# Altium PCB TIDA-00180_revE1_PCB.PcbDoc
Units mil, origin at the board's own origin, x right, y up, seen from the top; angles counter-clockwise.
Board outline 3535 x 2012 mil, 4 copper layers (Top Layer, mid layer 1-GND, mid layer 2-VCC, Bottom Layer), stack 90 mil thick; 92 components, 45 nets, 244 pads, 119 vias.
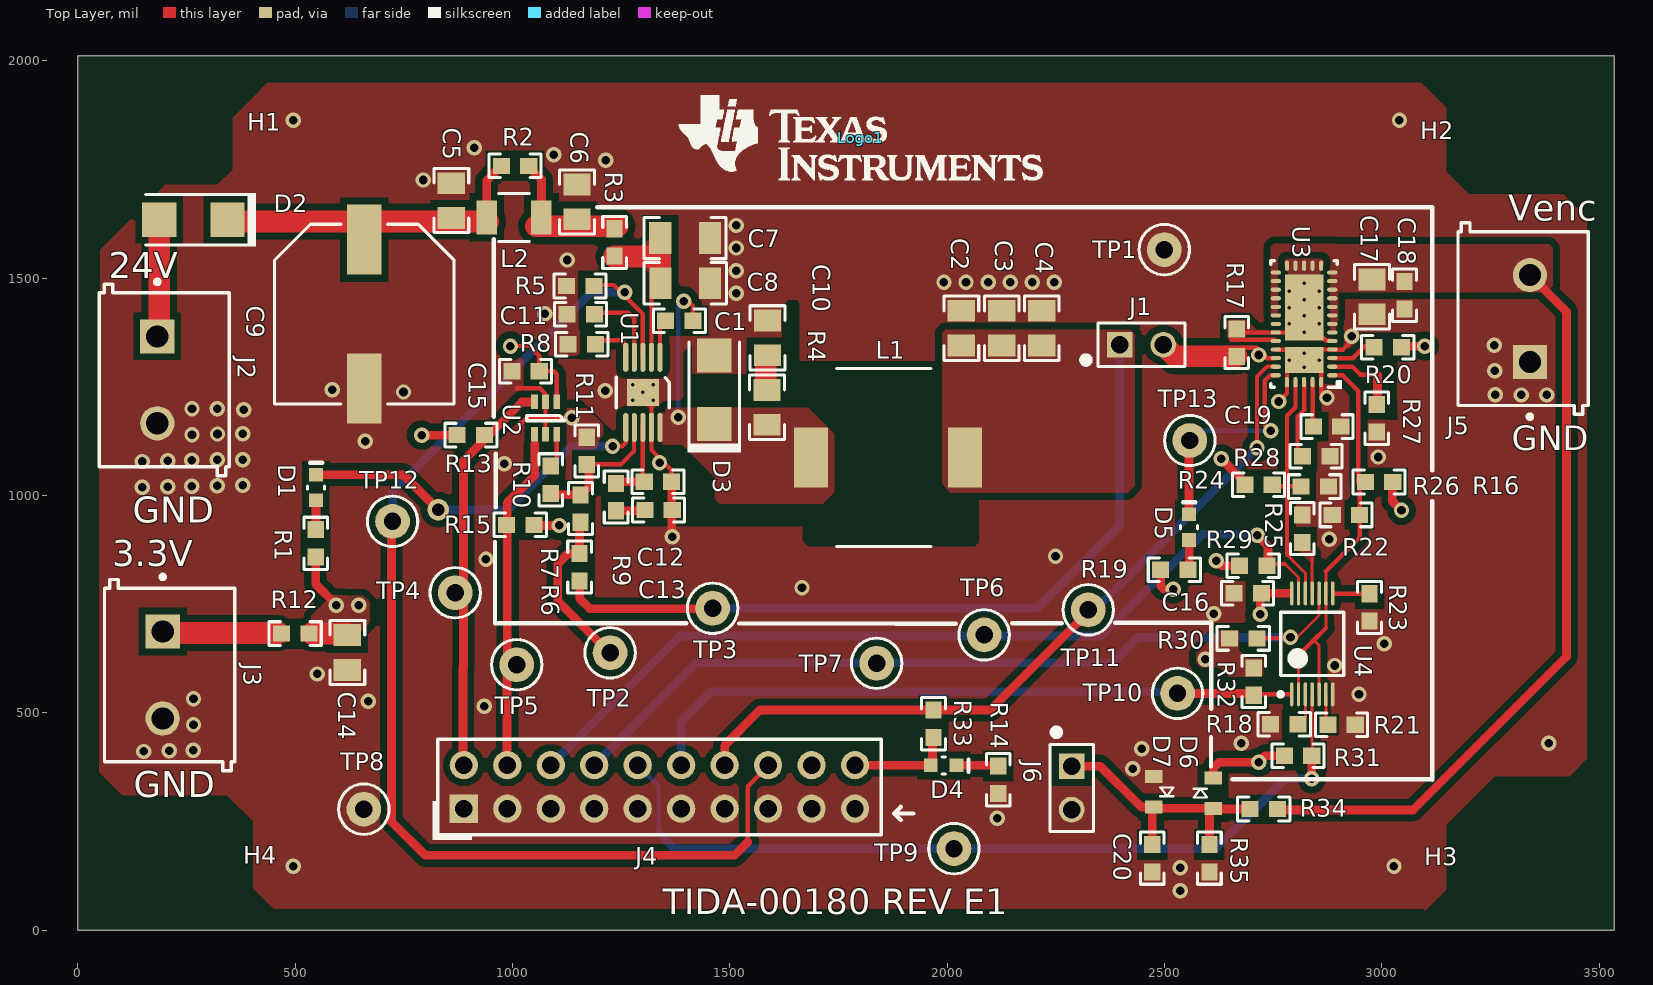
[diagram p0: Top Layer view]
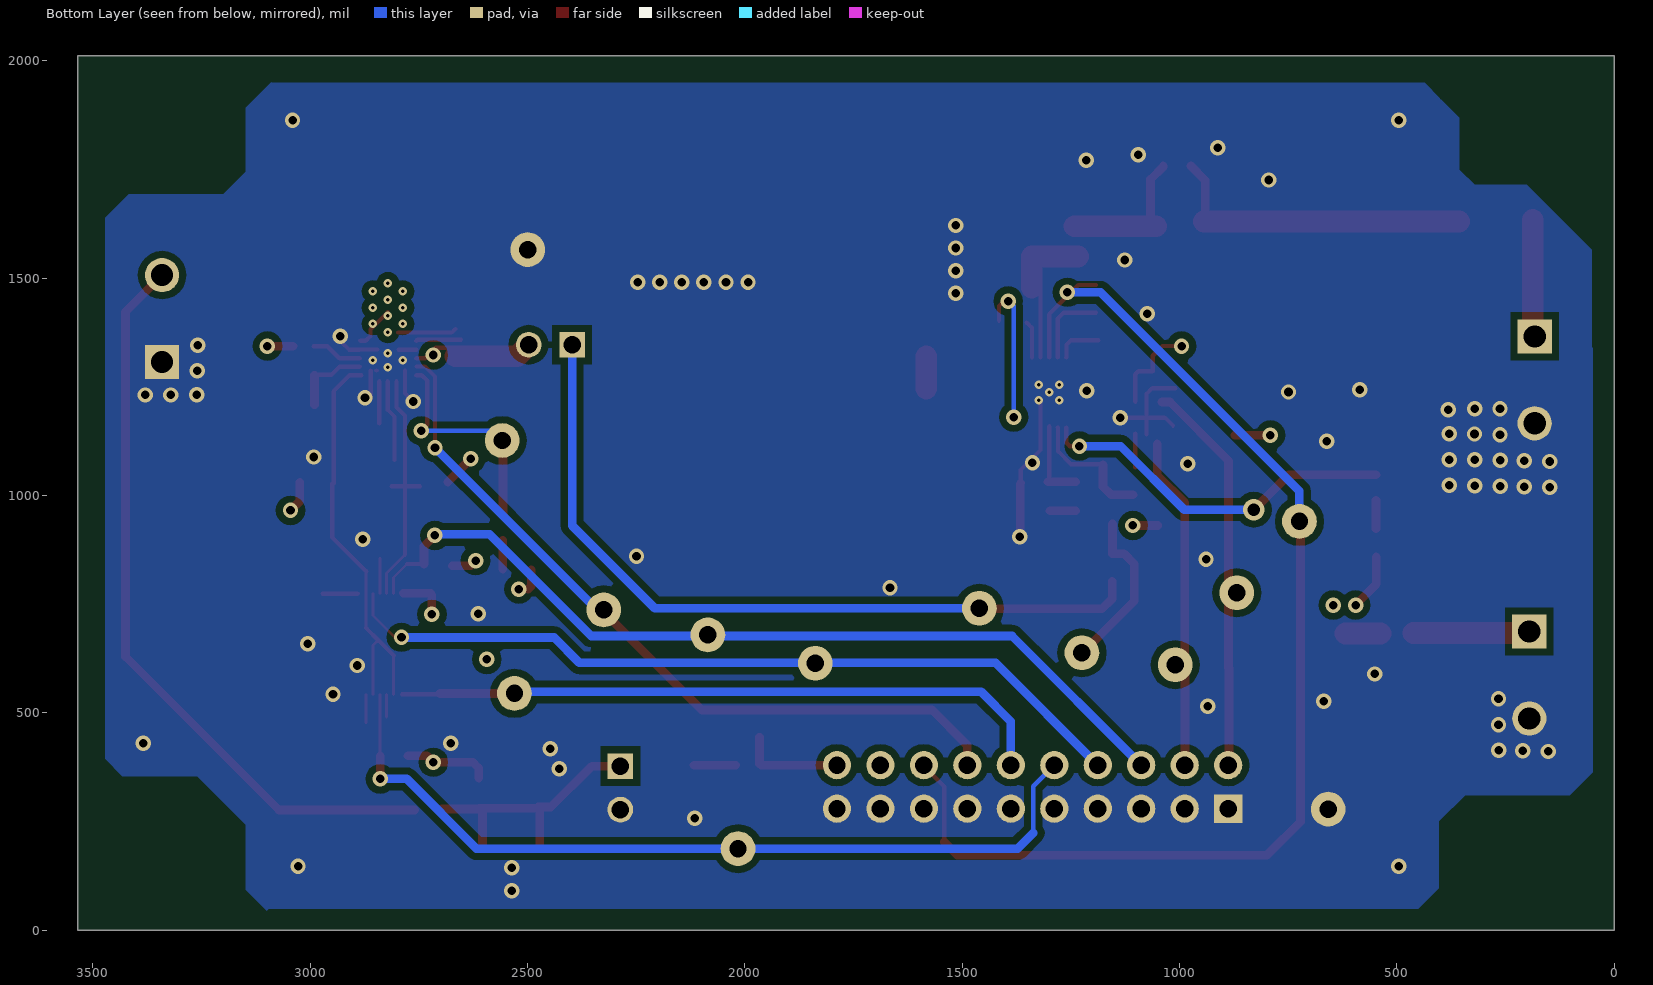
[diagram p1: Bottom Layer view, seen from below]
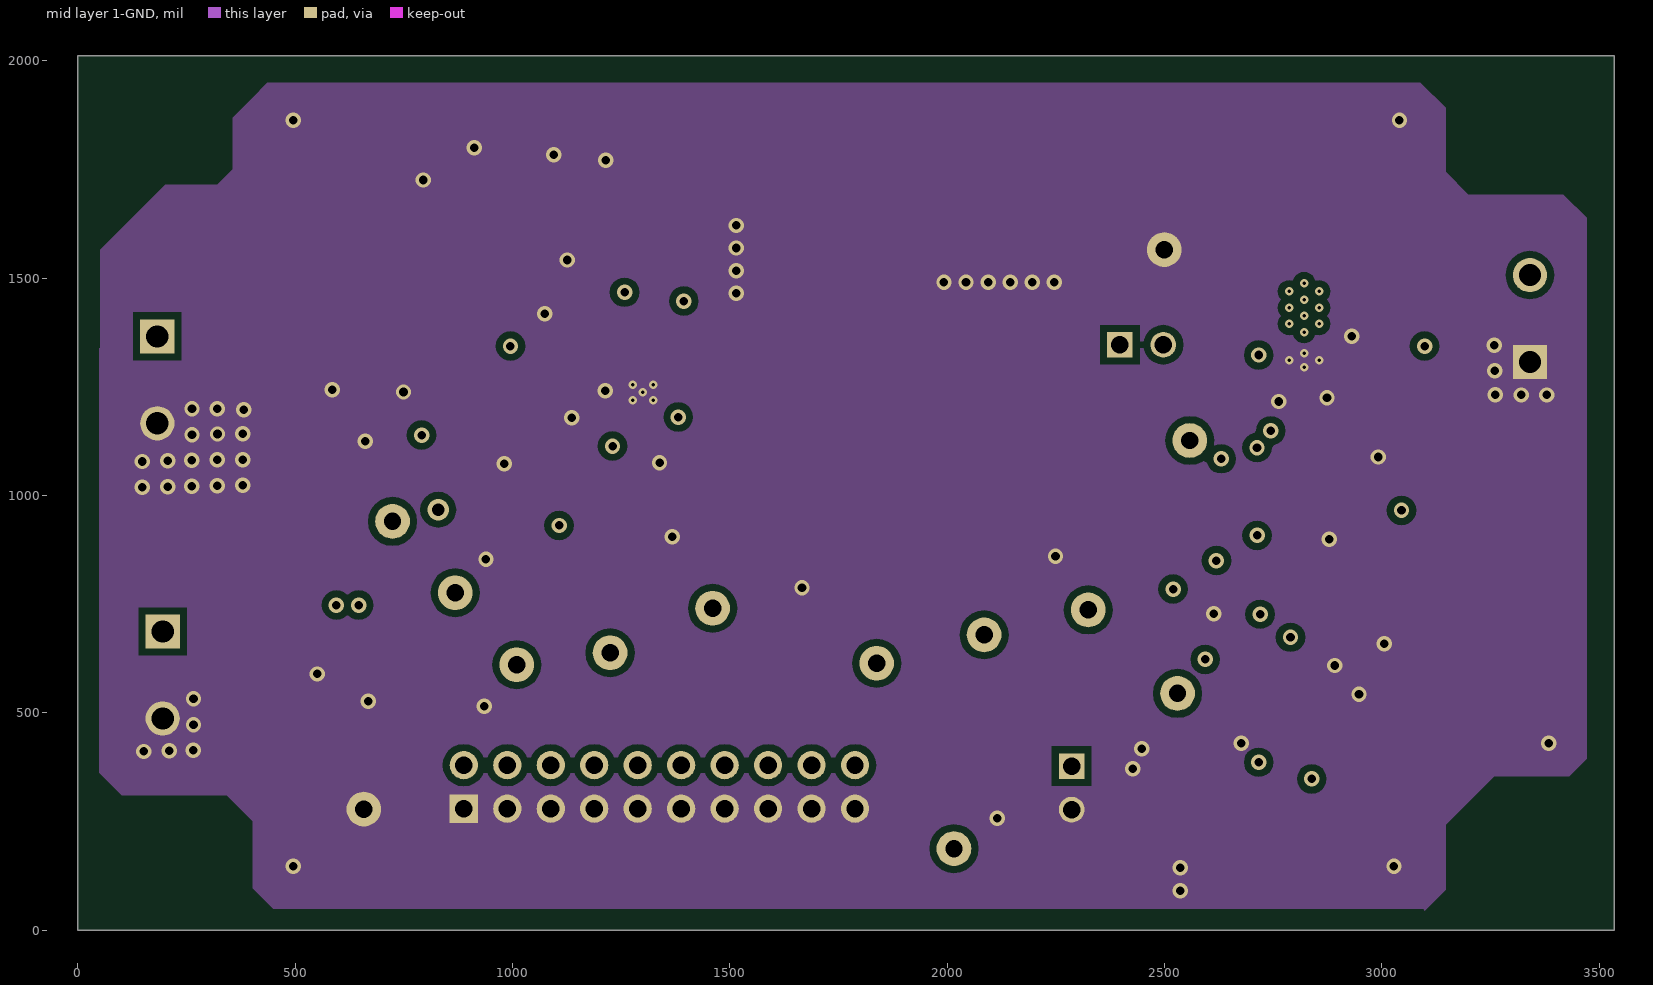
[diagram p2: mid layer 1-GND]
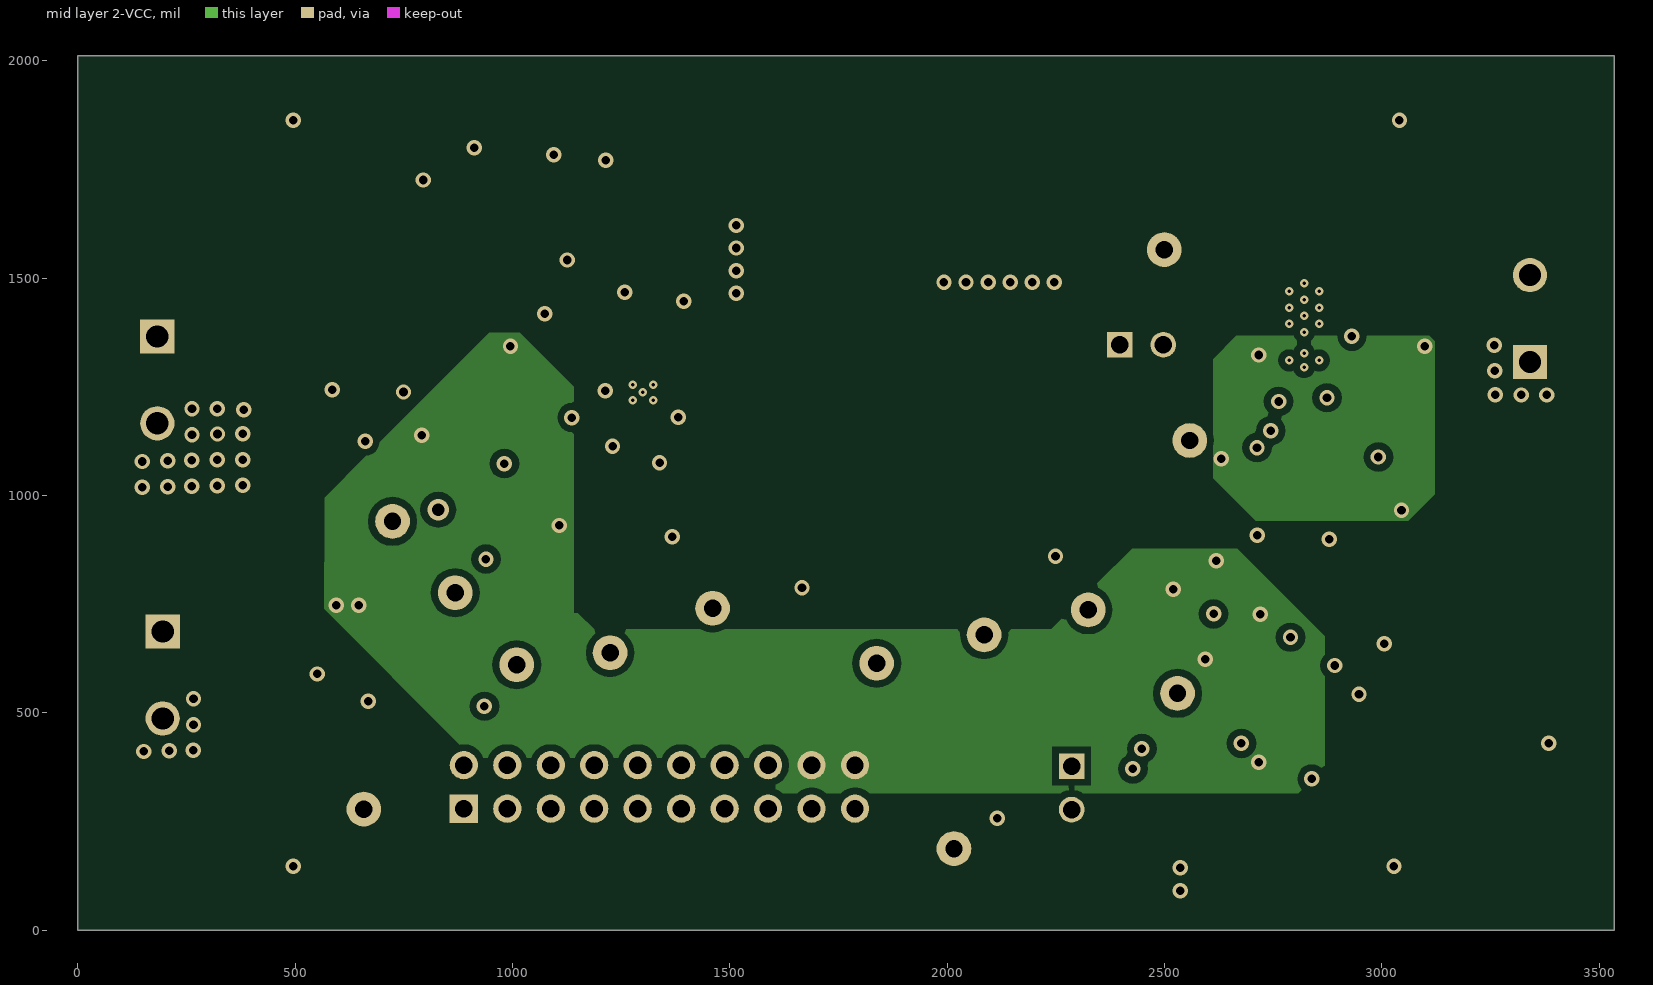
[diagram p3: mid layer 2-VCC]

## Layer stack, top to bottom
Top Layer: signal copper 1.4
Dielectric: prepreg 59.2, FR-4, Dk 4.8
mid layer 1-GND: signal copper 1.4
Dielectric: core 12.6, FR-4, Dk 4.8
mid layer 2-VCC: signal copper 1.4
Dielectric: prepreg 12.6, FR-4, Dk 4.8
Bottom Layer: signal copper 1.4

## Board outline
0,0 3535,0 3535,2012 0,2012

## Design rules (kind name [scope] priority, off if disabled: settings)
AcuteAngle [All] p1: minimum=4.50000000000000E+0001 checktracksonly=FALSE
AssemblyTestPointUsage [All] p1: valid=2
Clearance Clearance_netR21_1u4 [InNet('NetR21_1') vs InPolygon] p1: gap=7
Clearance Clearance_BoardEdge_MountingHoles [OnCopper and InComponentClass('Mounting Holes') vs IsKeepOut] p2: gap=40
Clearance Clearance_BoardEdge_Poly [OnCopper and InPoly vs IsKeepOut] p3: gap=25
Clearance Clearance_BoardEdge [OnCopper and Not InComponentClass('Logo') and not InComponentClass('FiducialMark') and not InRegion(1000,500,4000,800) and Not IsKeepout vs IsKeepOut] p4: gap=75
Clearance Clearance_Poly [InPolygon] p5: gap=15.75
Clearance Clearance_U2 [(ObjectKind = 'Pad') And (Component = 'U2') vs (ObjectKind = 'Pad') And (Component = 'U2')] p6: gap=7.8
Clearance Clearance_U4 [(ObjectKind = 'Pad') And (Component = 'U4') vs (ObjectKind = 'Pad') And (Component = 'U4')] p7: gap=7
Clearance Clearance_U1 [(ObjectKind = 'Pad') And (Component = 'U1') vs (ObjectKind = 'Pad') And (Component = 'U1')] p8: gap=7
Clearance [All] p9: gap=8
ComponentClearance ComponentClearance_Shunt [InComponentClass('Header') vs InComponentClass('Shunt')] p1: gap=0 collisioncheckmode=3 verticalgap=0 showdistances=FALSE
ComponentClearance ComponentClearance_Logo [InComponentClass('Logo')] p2: gap=50 collisioncheckmode=3 verticalgap=10 showdistances=FALSE
ComponentClearance ComponentClearance_ScrewToNut [(HasFootprint('NY PMS 440 0025 PH')) vs (HasFootprint('Keystone_1902C'))] p3: gap=5 collisioncheckmode=3 verticalgap=10 showdistances=FALSE
ComponentClearance ComponentClearance_MountingHoles [InComponentClass('Mounting Holes')] p4: gap=250 collisioncheckmode=3 verticalgap=100000 showdistances=FALSE
ComponentClearance ComponentClearance_SmallPassives [HasFootprint('0201*') or HasFootprint('0402*') or HasFootprint('0508') or HasFootprint('0603*') or HasFootprint('0612') or HasFootprint('0805*') or HasFootprint('0815*') or HasFootprint('0830*') or HasFootprint('1206*') or HasFootprint('1210*') or HasFootprint('1808*') or HasFootprint('1812*') or HasFootprint('1825*') or HasFootprint('2010*') or HasFootprint('2220*') or HasFootprint('2225*') or HasFootprint('2512*') or HasFootprint('2728*') or HasFootprint('3518*') vs HasFootprint('0201*') or HasFootprint('0402*') or HasFootprint('0508') or HasFootprint('0603*') or HasFootprint('0612') or HasFootprint('0805*') or HasFootprint('0815*') or HasFootprint('0830*') or HasFootprint('1206*') or HasFootprint('1210*') or HasFootprint('1808*') or HasFootprint('1812*') or HasFootprint('1825*') or HasFootprint('2010*') or HasFootprint('2220*') or HasFootprint('2225*') or HasFootprint('2512*') or HasFootprint('2728*') or HasFootprint('3518*')] p5: gap=20 collisioncheckmode=3 verticalgap=10 showdistances=FALSE
ComponentClearance ComponentClearance_THtoSMT [IsThruComponent vs IsSMTComponent] p6: gap=100 collisioncheckmode=3 verticalgap=30 showdistances=FALSE
ComponentClearance ComponentClearance_THtoTH [IsThruComponent vs IsThruComponent] p7: gap=118.11 collisioncheckmode=3 verticalgap=30 showdistances=FALSE
ComponentClearance [All] p8: gap=40 collisioncheckmode=3 verticalgap=10 showdistances=FALSE
DiffPairsRouting [All] p1: maxlimit=100 minlimit=10 mostfreqgap=10 maxuncoupledlength=1000
FabricationTestPointUsage TestPointUsage [All] p1: valid=2 allowmultiple=FALSE
FabricationTestpoint Testpoint [All] p1: side=3 testpointundercomponent=TRUE minsize=40 maxsize=100 preferedsize=60 minholesize=0 maxholesize=40 preferedholesize=32 testpointgrid=1 allowsidetop=TRUE allowsidebottom=TRUE usegrid=TRUE gridtolerance=0.01
FanoutControl Fanout_LCC [IsLCC] p1: bgadir=Out bgaviamode=Centered fanoutstyle=Auto fanoutdirection=Alternating viagrid=1 // Fanout_LCC (Default Rule)
FanoutControl Fanout_BGA [IsBGA] p2: bgadir=Out bgaviamode=Centered fanoutstyle=Auto fanoutdirection=Alternating viagrid=1 // Fanout_BGA (Default Rule)
FanoutControl Fanout_Default [All] p4: bgadir=Out bgaviamode=Centered fanoutstyle=Auto fanoutdirection=Alternating viagrid=1 // Fanout_Default (Default Rule)
FanoutControl Fanout_Small [(CompPinCount < 5)] p5: bgadir=Out bgaviamode=Centered fanoutstyle=Auto fanoutdirection=OutThenIn viagrid=1 // Fanout_Small (Default Rule)
HoleSize HoleSize_CompoentPAD [((Component =U1)or (Component =U3)) and isVia] p1: absolutevalues=TRUE maxlimit=251 minlimit=7.87 maxpercent=80.000 minpercent=20.000
HoleSize [All] p2: absolutevalues=TRUE maxlimit=251 minlimit=8 maxpercent=80.000 minpercent=20.000
MinimumAnnularRing MinimumAnnularRing_ThermalPadVias_U1 [IsVia and (Component = U1)] p1: minimumring=3.9
MinimumAnnularRing MinimumAnnularRing_ThermalPadVias_U3 [IsVia and (Component = U3)] p2: minimumring=3.9
MinimumAnnularRing MinimumAnnularRing_ThermalPadVias [IsVia and InAnyComponent] p3: minimumring=5.91
MinimumAnnularRing [All] p4: minimumring=7.87
MinimumSolderMaskSliver MinimumSolderMaskSliver_ComponentPAD [Component = U2 vs Component = U2] p1: minsoldermaskwidth=1.77
MinimumSolderMaskSliver MinimumSolderMaskSliver_Logo [InComponentClass('Logo') vs InComponentClass('Logo')] p2: minsoldermaskwidth=0.7
MinimumSolderMaskSliver [All] p3: minsoldermaskwidth=3.94
PlaneConnect [All] p1: planeconnectstyle=Relief reliefexpansion=10 reliefentries=4 reliefconductorwidth=10 reliefairgap=10
PolygonConnect [All] p1: connectstyle=Direct reliefconductorwidth=10 reliefentries=4 polygonreliefangle="90 Angle" airgapwidth=10
RoutingVias ComponentPadVias [IsVia and ((Component = U1)or (Component = U3))] p1: holewidth=7.87 width=7.87 viastyle="Through Hole" minholewidth=7.84 minwidth=7.84 maxholewidth=12.99 maxwidth=23.62
RoutingVias ThermalPadVias [IsVia and InAnyComponent] p2: holewidth=7.87 width=19.68 viastyle="Through Hole" minholewidth=11.81 minwidth=19.68 maxholewidth=12.99 maxwidth=23.62
RoutingVias [All] p3: holewidth=16 width=34 viastyle="Through Hole" minholewidth=11.81 minwidth=26 maxholewidth=40 maxwidth=65
SMDToCorner SMDToCorner_TPS24750 [InNet('NetR17_1')] p1: distance=18000
SMDToCorner [All] p2: distance=30000
SilkToSilkClearance [All] p1: silktosilkclearance=5
SilkscreenOverComponentPads [All] p1: minsilkscreentomaskgap=5
SolderMaskExpansion [All] p1: expansion=1.97
Width [All] p1: maxlimit=100 minlimit=6 preferedwidth=10 checkconnectedcopper=TRUE
14 further rules are at their usual default settings.

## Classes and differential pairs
component class Screw: H1 H2 H3 H4
component class TIDA-00180_revE1_PS: C1 C2 C3 C4 C5 C6 C7 C8 C9 C10 C11 C12 C13 C14 C15 D1 D2 D3 D4 J1 J2 J3 J4 L1 L2 R1 R2 R3 R4 R5 R6 R7 R8 R9 R10 R11 R12 R13 R14 R15 TP1 TP2 TP3 TP4 TP5 TP6 TP7 TP8 TP9 TP10 TP11 TP12 U1 U2
component class TIDA-00180_revE1_PR: C16 C17 C18 C19 C20 D5 D6 D7 J5 J6 R16 R17 R18 R19 R20 R21 R22 R23 R24 R25 R26 R27 R28 R29 R30 R31 R32 R33 R34 R35 TP13 U3 U4
component class Logo: Logo1
component class TIDA-00180_revE1_Block_Diagram: H1 H2 H3 H4 Logo1

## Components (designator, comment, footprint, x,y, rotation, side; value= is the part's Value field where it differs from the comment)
C1 "GRM188R71H104KA93D" 0603 1384.11,1402.53 r180 top
C2 "C2012X5R1H475K125AB" 0805_HV 2032.87,1385.26 r90 top
C3 "C2012X5R1H475K125AB" 0805_HV 2125.88,1385.26 r90 top
C4 "C2012X5R1H475K125AB" 0805_HV 2217.87,1385.26 r90 top
C5 "GRM21BR71H105KA12L" 0805_HV 859.54,1678.82 r90 top
C6 "GRM21BR71H105KA12L" 0805_HV 1148.54,1675.52 r90 top
C7 "GRM31CR61H225KA88L" 1206 1397.34,1592.55 r0 top
C8 "GRM31CR61H225KA88L" 1206 1397.58,1488.78 r0 top
C9 "EEE-FK1J101P" SM_RADIAL_G 659.3,1417.66 r270 top
C10 "C2012X5R1H475K125AB" 0805_HV 1586.85,1362.86 r90 top
C11 "GRM188R71C222KA01D" 0603 1156.99,1417.35 r180 top
C12 "GRM1885C1H100JA01D" 0603 1334.71,1031.72 r0 top
C13 "GRM188R71E682KA01D" 0603 1336.36,966.99 r0 top
C14 "C2012X5R1E106K125AB" 0805_HV 620.33,639.07 r270 top
C15 "06033D104KAT2A" 0603 1030.16,1286.14 r180 top
C16 "06033D104KAT2A" 0603 2691.54,775.13 r180 top
C17 "C2012X5R1H475K125AB" 0805_HV 2977.6,1457.36 r270 top
C18 "GRM188R71H104KA93D" 0603 3052.3,1460.87 r270 top
C19 "GRM188R71C683KA01D" 0603 2874.35,1158.77 r0 top
C20 "GRM188R70J473KA01D" 0603 2472.36,165.89 r270 top
D1 "LG L29K-G2J1-24-Z" "LG L29K_GREEN" 547.97,1018.54 r90 top
D2 "MBRA160T3G" SMA 266.09,1634.72 r180 top
D3 "MBRA160T3G" SMA 1464.43,1243.38 r90 top
D4 "LG L29K-G2J1-24-Z" "LG L29K_GREEN" 1992.03,379.36 r0 top
D5 "LG L29K-G2J1-24-Z" "LG L29K_GREEN" 2556.72,927.46 r90 top
D6 "D_SCHOT_CDBU00340" C603-DIODE 2612.76,315.52 r270 top
D7 "D_SCHOT_CDBU00340" C603-DIODE 2475.68,318.57 r90 top
H1 "MPMS 003 0005 PH" BuildingFastener_MPMS_003_0005_PH 221.86,1843.88 r0 top
H2 "MPMS 003 0005 PH" BuildingFastener_MPMS_003_0005_PH 3310.72,1843.88 r0 top
H3 "MPMS 003 0005 PH" BuildingFastener_MPMS_003_0005_PH 3310.72,166.78 r0 top
H4 "MPMS 003 0005 PH" BuildingFastener_MPMS_003_0005_PH 221.86,166.78 r0 top
J1 "PEC02SAAN" CONN_PEC02SAAN 2447.57,1346.96 r0 top
J2 "OSTTC022162" On-Shore_OSTTC022162 198.87,1266.26 r270 top
J3 "OSTTC022162" On-Shore_OSTTC022162 211.13,587.35 r270 top
J4 "PEC10DAAN" SULLINS_PEC10DAAN 1338.28,329.85 r90 top
J5 "OSTTC022162" On-Shore_OSTTC022162 3325.19,1407.29 r90 top
J6 "PEC02SAAN" CONN_PEC02SAAN 2286.62,327.6 r270 top
L1 "7447713151" WE-PD-1030 1864.19,1087.93 r0 top
L2 "NLCV32T-4R7M-PFR" NLCV32 1003.74,1640.08 r0 top
Logo1 "Texas Instruments" TI_Stacked_Overlay_Small 1801.63,1823.28 r0 top
R1 "CRCW0603560RJNEA" 0603 547.3,890.29 r270 top
R2 "CRCW060310R0JNEAHP" 0603 1006.03,1758.58 r0 top
R3 "CRCW06030000Z0EA" 0603 1235.04,1582.34 r270 top
R4 "CRCW080510K0JNEA" 0805_HV 1585.88,1203.08 r270 top
R5 "CRCW06034K70JNEA" 0603 1155.86,1482.42 r180 top
R6 "CRCW060351R0JNEA" 0603 1154.64,835.42 r90 top
R7 "CRCW060343K2FKEA" 0603 1156.53,970.1 r270 top
R8 "CRCW0603165KFKEA" 0603 1159.6,1348.34 r0 top
R9 "CRCW060349K9FKEA" 0603 1238.62,996.69 r90 top
R10 "CRCW06032K49FKEA" 0603 1088.35,1036.34 r270 top
R11 "CRCW060346K4FKEA" 0603 1170.9,1102.89 r270 top
R12 "CRCW06031R00FKEA" 0603 500.21,682.58 r0 top
R13 "CRCW06034K70JNEA" 0603 904.42,1139.2 r0 top
R14 "CRCW0603560RJNEA" 0603 2117.59,346.31 r90 top
R15 "CRCW06034K70JNEA" 0603 1017.96,932.67 r0 top
R16 "CRCW060375K0FKEA" 0603 2993.9,1031.27 r0 top
R17 "ERJ-3RSFR10V" 0603 2666.39,1351.98 r270 top
R18 "CRCW060316K9FKEA" 0603 2775.65,473.89 r180 top
R19 "CRCW0603560RJNEA" 0603 2522.9,829.27 r180 top
R20 "CRCW060380R6FKEA" 0603 3013.84,1341.06 r0 top
R21 "CRCW060312K7FKEA" 0603 2907.61,472.88 r0 top
R22 "CRCW060322K1FKEA" 0603 2917.59,955.52 r0 top
R23 "CRCW060310K0FKEA" 0603 2971.96,742.76 r270 top
R24 "CRCW060349K9FKEA" 0603 2716.63,1025.03 r180 top
R25 "CRCW060321K5FKEA" 0603 2817.01,924.07 r90 top
R26 "CRCW060323K7FKEA" 0603 2845.96,1020.78 r180 top
R27 "CRCW06031K37FKEA" 0603 2988.68,1177.92 r90 top
R28 "CRCW06034K99FKEA" 0603 2849.14,1090.29 r180 top
R29 "CRCW06034K70JNEA" 0603 2704.29,838.46 r180 top
R30 "CRCW06034K70JNEA" 0603 2681.36,671.48 r180 top
R31 "CRCW06034K70JNEA" 0603 2807.52,401.61 r180 top
R32 "CRCW06034K70JNEA" 0603 2705.81,572.33 r90 top
R33 "CRCW06034K70JNEA" 0603 1968.77,475.15 r270 top
R34 "CRCW060312K1FKEA" 0603 2728.5,278.97 r0 top
R35 "CRCW06033K00JNEA" 0603 2603.62,165.89 r90 top
TP1 "5001" Keystone5001 2499.79,1566.01 r90 top
TP2 "5000" Keystone5000 1224.73,638.39 r270 top
TP3 "5000" Keystone5000 1460.62,740.79 r270 top
TP4 "5002" Keystone5002 868.44,776.48 r90 top
TP5 "5002" Keystone5002 1009.95,610.94 r90 top
TP6 "5002" Keystone5002 2085.28,679.59 r90 top
TP7 "5002" Keystone5002 1838,614.34 r90 top
TP8 "5001" Keystone5001 658.22,278.72 r90 top
TP9 "5002" Keystone5002 2015.87,187.84 r90 top
TP10 "5002" Keystone5002 2530.29,544.95 r90 top
TP11 "5002" Keystone5002 2324.85,737.05 r90 top
TP12 "5002" Keystone5002 724.27,940.68 r90 top
TP13 "5002" Keystone5002 2558.54,1126.83 r90 top
U1 "TPS54040ADGQ" DGQ0010D_N 1300.22,1237.5 r270 top
U2 "TPL0401A-10DCKR" DCK0006A_N 1076.32,1178.49 r270 top
U3 "TPS24750RUV" RUV0036A 2821.39,1394.98 r180 top
U4 "SN74CB3Q3125DGV" DGV0014A_N 2840.12,658.94 r90 top

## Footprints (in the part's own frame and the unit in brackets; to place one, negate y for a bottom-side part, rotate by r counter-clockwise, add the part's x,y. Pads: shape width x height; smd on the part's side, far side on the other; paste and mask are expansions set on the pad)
0603 [mm] "0603 from SM-752 data"
  rect 1x0.95 smd: 1(-0.8,0) 2(0.8,0)
  silkscreen extent -1.52,-0.69 1.52,0.69, body extent -0.87,-0.47 0.87,0.47, height 0.85
0805_HV [mil] "0805 with 30mil clearance between pads"
  rect 50x63 smd: 1(-40,0) 2(40,0)
  silkscreen extent -74,-40 74,40, body extent -43,-29 43,29, height 43
1206 [mm] "1206 from SM-752 data"
  rect 1.3x1.85 smd: 1(-1.45,0) 2(1.45,0)
  silkscreen extent -2.4,-1.21 2.4,1.21, body extent -1.7,-0.9 1.7,0.9, height 1.35
BuildingFastener_MPMS_003_0005_PH [mil] "MACHINE SCREW PAN PHILLIPS M3"
  round 1 on Mech3: 0(0,0)
  body extent -118,-118 118,118, height 93
C603-DIODE [mil]
  rect 30x40 smd: 1(-35,0) 2(35,0)
  silkscreen extent -10,-45 10,-15
CONN_PEC02SAAN [mm] "SULLINS"
  rect 1.5x1.5 hole 1.016: 1(-1.27,0)
  round 1.5 hole 1.016: 2(1.27,0)
  silkscreen extent -3.45,-1.27 2.54,1.27, body extent -2.54,-1.27 2.54,1.27, height 8.38
DCK0006A_N [mm] "SOT23, 6-Leads, Body 2x1.3mm, Pitch 0.65mm, Lead Span 2.1mm, IPC Medium Density"
  rect 0.85x0.4 smd: 1(-0.95,0.65) 2(-0.95,0) 3(-0.95,-0.65) 4(0.95,-0.65) 5(0.95,0) 6(0.95,0.65)
  silkscreen extent -0.15,-1.1 0.15,1.1, body extent -1.14,-1 1.14,1, height 0.94
DGQ0010D_N [mm] "TSSOP, 10-Leads, Body 3x3mm, Pitch 0.5mm, Thermal Pad 1.88x1.57mm, IPC Medium Density"
  oval 1.7x0.3 smd: 1(-2.05,1) 2(-2.05,0.5) 3(-2.05,0) 4(-2.05,-0.5) 5(-2.05,-1) 6(2.05,-1) 7(2.05,-0.5) 8(2.05,0) 9(2.05,0.5) 10(2.05,1)
  rect 1.57x1.88 smd: 11(0,0)
  silkscreen extent -0.9,-1.55 0.9,1.55, body extent -1.55,-1.55 1.55,1.55, height 1.1
DGV0014A_N [mm] "TSSOP, 14-Leads, Body 3.60x4.40mm, Pitch 0.40mm, IPC Medium Density"
  oval 1.4x0.2 smd: 1(-2.95,1.2) 2(-2.95,0.8) 3(-2.95,0.4) 4(-2.95,0) 5(-2.95,-0.4) 6(-2.95,-0.8) 7(-2.95,-1.2) 8(2.95,-1.2) 9(2.95,-0.8) 10(2.95,-0.4) 11(2.95,0) 12(2.95,0.4) 13(2.95,0.8) 14(2.95,1.2)
  silkscreen extent -3.07,-1.85 1.85,1.97, body extent -2.25,-1.85 2.25,1.85, height 1.2
Keystone5000 [mil] "For Keystone 500x miniature loop terminals"
  round 80 hole 40: 1(0,0)
  silkscreen extent -58,-58 58,58, body extent -49,-49 49,49, height 182
Keystone5001 [mil] "For Keystone 500x miniature loop terminals"
  round 80 hole 40: 1(0,0)
  silkscreen extent -58,-58 58,58, body extent -49,-49 49,49, height 182
Keystone5002 [mil] "For Keystone 500x miniature loop terminals"
  round 80 hole 40: 1(0,0)
  silkscreen extent -58,-58 58,58, body extent -49,-49 49,49, height 182
"LG L29K_GREEN" [mm] "OSRAM"
  rect 0.8x0.8 smd paste-0.4: 1(-0.75,0) 2(0.75,0)
  silkscreen extent -0.1,-0.5 1.45,0.5, body extent -0.9,-0.45 0.9,0.45, height 0.67
NLCV32 [mm] "TDK"
  rect 1.2x2 smd: 1(-1.6,0) 2(1.6,0)
  silkscreen extent -0.9,-1.4 0.9,1.4, body extent -1.7,-1.35 1.7,1.35, height 2.4
On-Shore_OSTTC022162 [mm] "THD, 2-Leads, Body 10.16x7.6mm, Pitch 5.08mm"
  rect 2x2 hole 1.3: 1(-2.54,-0.4)
  round 2 hole 1.3: 2(2.54,-0.4)
  silkscreen extent -5.85,-3.8 5.6,3.8, body extent -5.58,-3.8 5.6,3.8, height 10.31
RUV0036A [mm]
  oval 0.6x0.24 smd: 1(-1.65,3) 2(-1.65,2.5) 3(-1.65,2) 4(-1.65,1.5) 5(-1.65,1) 6(-1.65,0.5) 7(-1.65,0) 8(-1.65,-0.5) 9(-1.65,-1) 10(-1.65,-1.5) 11(-1.65,-2) 12(-1.65,-2.5) 13(-1.65,-3) 19(1.65,-3) 20(1.65,-2.5) 21(1.65,-2) 22(1.65,-1.5) 23(1.65,-1) 24(1.65,-0.5) 25(1.65,0) 26(1.65,0.5) 27(1.65,1) 28(1.65,1.5) 29(1.65,2) 30(1.65,2.5) 31(1.65,3)
  oval 0.24x0.6 smd: 14(-1,-3.4) 15(-0.5,-3.4) 16(0,-3.4) 17(0.5,-3.4) 18(1,-3.4) 32(1,3.4) 33(0.5,3.4) 34(0,3.4) 35(-0.5,3.4) 36(-1,3.4)
  rect 2.25x1.514 smd paste-1: 37(0,2.118)
  rect 2.25x3.836 smd paste-1.2: 38(0,-0.957)
  silkscreen extent -2.22,-3.7 1.95,3.8, body extent -1.82,-3.57 1.82,3.57, height 1.02
SM_RADIAL_G [mm] "10 x 10.2mm:  Panasonic G"
  rect 4.1x2 smd: 1(-4.35,0) 2(4.35,0)
  silkscreen extent -5.25,-5.25 5.25,5.25, body extent -5.26,-5.26 5.26,5.26, height 10.5
SMA [mm] "Molded Diode, 2-Leads, Body 4.3x2.6mm, IPC Medium Density, based on OnSemi component dimensions and land pattern"
  rect 2x2 smd: 1(-2,0) 2(2,0)
  silkscreen extent -3.66,-1.57 2.79,1.57, body extent -2.6,-1.3 2.6,1.3, height 2.42
SULLINS_PEC10DAAN [mm] "SULLINS"
  rect 1.65x1.65 hole 1.016: 1(-1.27,11.43)
  round 1.65 hole 1.016: 2(1.27,11.43) 3(-1.27,8.89) 4(1.27,8.89) 5(-1.27,6.35) 6(1.27,6.35) 7(-1.27,3.81) 8(1.27,3.81) 9(-1.27,1.27) 10(1.27,1.27) 11(-1.27,-1.27) 12(1.27,-1.27) 13(-1.27,-3.81) 14(1.27,-3.81) 15(-1.27,-6.35) 16(1.27,-6.35) 17(-1.27,-8.89) 18(1.27,-8.89) 19(-1.27,-11.43) 20(1.27,-11.43)
  silkscreen extent -3.11,-12.96 2.79,13.25, body extent -2.79,-12.96 2.79,12.96, height 9.08
TI_Stacked_Overlay_Small [mil]
  silkscreen extent -418,-98 418,98
WE-PD-1030 [mm] "WERTH"
  rect 2x3.5 smd: 1(-4.5,0) 2(4.5,0)
  silkscreen extent -3,-5.2 2.5,5.2, body extent -5.15,-5.15 5.15,5.15, height 3

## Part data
C1 C18: "CAP, CERM, 0.1 µF, 50 V, +/- 10%, X7R, 0603"
C2 C3 C4 C10 C17: "CAP, CERM, 4.7 µF, 50 V, +/- 10%, X5R, 0805"
C5 C6: "CAP, CERM, 1uF, 50V, +/-10%, X7R, 0805"
C7 C8: "CAP, CERM, 2.2uF, 50V, +/-10%, X5R, 1206"
C9: "CAP, AL, 100uF, 63V, +/-20%, 0.35 ohm, SMD"
C11: "CAP, CERM, 2200pF, 16V, +/-10%, X7R, 0603"
C12: "CAP, CERM, 10 pF, 50 V, +/- 5%, C0G/NP0, 0603"
C13: "CAP, CERM, 6800 pF, 25 V, +/- 10%, X7R, 0603"
C14: "CAP, CERM, 10uF, 25V, +/-10%, X5R, 0805"
C15 C16: "CAP, CERM, 0.1uF, 25V, +/-10%, X5R, 0603"
C19: "CAP, CERM, 0.068 µF, 16 V, +/- 10%, X7R, 0603"
C20: "CAP, CERM, 0.047 µF, 6.3 V, +/- 10%, X7R, 0603"
D1 D4 D5: "LED, Green, SMD"
D2 D3: "Diode, Schottky, 60V, 1A, SMA"
D6 D7: "Diode, Schottky, 30mA, 40V"
H1 H2 H3 H4: "MACHINE SCREW PAN PHILLIPS M3 5mm"
J1 J6: "Header, 100mil, 2x1, Tin plated, TH"
J2 J3 J5: "Terminal Block, 2-pole, 200mil, TH"
J4: "Header, 10x2, 2.54mm, TH"
L1: "Inductor, Shielded Drum Core, Ferrite, 150uH, 0.7A, 0.57 ohm, SMD"
L2: "Inductor, Wirewound, Ferrite, 4.7uH, 0.9A, 0.2 ohm, SMD"
Logo1: library part TI_Logo, "Texas Instrument Corporate Signature"
R1 R14 R19: "RES, 560, 5%, 0.1 W, 0603"
R2: "RES, 10 ohm, 5%, 0.25W, 0603"
R3: "RES, 0 ohm, 5%, 0.1W, 0603"
R4: "RES, 10k ohm, 5%, 0.125W, 0805"
R5 R13 R15 R29 R30 R31 R32 R33: "RES, 4.7k ohm, 5%, 0.1W, 0603"
R6: "RES, 51 ohm, 5%, 0.1W, 0603"
R7: "RES, 43.2 k, 1%, 0.1 W, 0603"
R8: "RES, 165k ohm, 1%, 0.1W, 0603"
R9 R24: "RES, 49.9 k, 1%, 0.1 W, 0603"
R10: "RES, 2.49 k, 1%, 0.1 W, 0603"
R11: "RES, 46.4 k, 1%, 0.1 W, 0603"
R12: "RES, 1.00, 1%, 0.1 W, 0603"
R16: "RES, 75.0 k, 1%, 0.1 W, 0603"
R17: "RES, 0.1, 1%, 0.1 W, 0603"
R18: "RES, 16.9 k, 1%, 0.1 W, 0603"
R20: "RES, 80.6, 1%, 0.1 W, 0603"
R21: "RES, 12.7 k, 1%, 0.1 W, 0603"
R22: "RES, 22.1 k, 1%, 0.1 W, 0603"
R23: "RES, 10.0 k, 1%, 0.1 W, 0603"
R25: "RES, 21.5 k, 1%, 0.1 W, 0603"
R26: "RES, 23.7 k, 1%, 0.1 W, 0603"
R27: "RES, 1.37 k, 1%, 0.1 W, 0603"
R28: "RES, 4.99k ohm, 1%, 0.1W, 0603"
R34: "RES, 12.1 k, 1%, 0.1 W, 0603"
R35: "RES, 3.0 k, 5%, 0.1 W, 0603"
TP1 TP8: "Test Point, Miniature, Black, TH"
TP2 TP3: "Test Point, Miniature, Red, TH"
TP4 TP5 TP6 TP7 TP9 TP10 TP11 TP12 TP13: "Test Point, Miniature, White, TH"
U1: "0.5 A, 42 V Step Down DC/DC Converter with Eco-mode, DGQ0010D"
U2: "128 TAPS Single Channel Digital Potentiometer with I2C Interface, DCK0006A"
U3: "2.5 to 18 V Positive Voltage 10A Integrated Hot-Swap Controller, RUV0036A"
U4: "Quadruple FET Bus Switch, 2.5-V/3.3-V Low-Voltage High-Bandwidth Bus Switch, DGV0014A"

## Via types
v1: diameter 35.43, hole 19.68, Top Layer to Bottom Layer, 98 vias
v2: diameter 19.68, hole 7.87, Top Layer to Bottom Layer, 19 vias
v3: diameter 50, hole 28, Top Layer to Bottom Layer, 1 vias
v4: diameter 35.43, hole 19.68, Top Layer to Bottom Layer, tented top, 1 vias

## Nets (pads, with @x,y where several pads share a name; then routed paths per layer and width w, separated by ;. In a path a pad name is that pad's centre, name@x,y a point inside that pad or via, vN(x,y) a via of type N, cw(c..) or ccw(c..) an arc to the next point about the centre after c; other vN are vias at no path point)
EFUSE_CTRL0: J4.12 R32.1 TP10.1 U4.1 | length 1535.9
  Top Layer w10: R32.1@2705.81,542.8 U4.1@2789.02,542.8
  Top Layer w20: TP10.1 R32.1@2701.7,544.95
  Bottom Layer w20: J4.12 1388.28,480.12 1456.63,548.47 TP10.1@2526.77,548.47 ; TP10.1@2530.29,548.47 TP10.1@2544.49,548.47
EFUSE_CTRL1: J4.10 R31.1 TP9.1 U4.4 | length 1945.5
  Top Layer w7: R31.1@2840.12,410.34 U4.4
  Top Layer w20: v1(2839.02,348.34) R31.1
  Bottom Layer w10: J4.10 1336.78,331.35 1336.78,223.83
  Bottom Layer w20: 1336.78,223.83 1372.86,187.74 2617.52,187.74 2778.12,348.34 v1(2839.02,348.34)
EFUSE_CTRL2: J4.8 R30.1 TP7.1 U4.10 | length 1938.6
  Top Layer w7: v1@2802.97,671.48 2855.87,724.37 U4.10
  Top Layer w10: R30.1 v1@2802.97,671.48
  Bottom Layer w20: J4.8 1423.75,615.33 2380.86,615.33 2439.03,673.49 v1@2789.62,673.49
  other v1: 2790.17,674.04
EFUSE_CTRL3: J4.6 R29.1 TP6.1 U4.13 | length 2040.7
  Top Layer w7: 2777.45,842.6 2808.63,811.42 U4.13
  Top Layer w10: R29.1@2738.27,842.6 2777.45,842.6
  Top Layer w20: v1(2713.25,908.39) 2738.27,883.38 R29.1@2738.27,842.6
  Bottom Layer w20: J4.6 1385.67,677.24 2353.84,677.24 2587.36,910.76 v1@2713.25,910.76
ENC_PS_ENABLE: J4.16 R5.1 TP12.1 U1.3 | length 2777.2
  Top Layer w10: R5.1@1192.27,1484.69 1233.03,1484.69 1300.22,1417.5 U1.3 ; 1541.49,202.93 1541.49,330.5 1588.28,377.28 J4.16
  Top Layer w20: TP12.1@721.9,938.74 721.9,249.88 799.22,172.55 1511.12,172.55 1541.49,202.93
  Bottom Layer w20: TP12.1@724.74,940.68 724.74,1010.45 1182.06,1467.77 v1(1258.28,1467.77)
ENC_PS_FAULT: J4.14 R33.1 TP11.1 U3.30 | length 1766
  Top Layer w10: v1(2713.12,1110.33) 2713.14,1273.72 2736.39,1296.98 U3.30@2754.86,1296.98
  Top Layer w20: J4.14 1488.28,425.46 1569.37,506.55 2099.54,506.55 TP11.1@2327.44,734.45
  Bottom Layer w20: TP11.1@2332.34,729.56 2408.67,805.88 2459.18,856.39 v1(2713.12,1110.33)
GND: C2.2 C3.2 C4.2 C5.2 C6.2 C7.2 C8.2 C9.2 C10.2 C11.2 C12.2 C13.2 C14.2 C15.2 C16.2 C17.2 C18.2 C19.2 C20.2 D3.2 D7.2 J2.2 J3.2 J4.1 J4.3 J4.5 J4.7 J4.9 J4.11 J4.13 J4.15 J4.17 J4.19 J5.1 J6.2 R5.2 R8.1 R11.1 R14.1 R18.2 R21.2 R22.1 R23.2 R25.2 R26.1 R27.1 R28.1 R35.1 TP1.1 TP8.1 U1.9 U1.11 U2.2 U2.5 U3.4 U3.28 U3.32 U3.36 U3.37 U4.7 | length 888.1
  Top Layer w10: 1009.68,1247.11 1063.31,1247.11 1076.32,1234.09 U2.2 1076.32,1179.46 ; 1015.35,1161.01 1033.8,1179.46 1076.32,1179.46 ; U2.5 1076.32,1179.46 ; v1(1136.61,1179.46) 1076.32,1179.46 ; U1.11@1319.91,1217.82 U1.9 1319.91,1104.8 1365.77,1058.93 C12.2@1365.77,1028.12 ; U3.28@2756.16,1335.63 U3.37@2796.79,1335.63 ; v1(2762.84,1216.58) 2782.02,1235.76 U3.37@2782.02,1287.35 ; U3.37@2845.72,1336.15 U3.4@2886.35,1336.15 ; U3.37@2847.05,1287.93 U3.37@2848.42,1287.93 ; v1@2860.76,1222.61 U3.37@2860.76,1287.35 ; U3.4 2911.08,1335.92 v1@2925.87,1350.71
  Top Layer w20: C12.2@1365.77,1028.12 1366.72,1027.17 v1@1366.72,914.8
  other v1: 2536.13,90.57 2536.73,143.46 495.92,147.21 3028.19,147.21 2115.45,257.44 2427.45,371.21 151.68,411.37 210.4,412.71 265.96,413.84 2448.33,417.87 2677.29,430.09 3384.17,429.97 266.29,473.3 935.59,515.38 668.15,527.12 266.29,532.75 2947.8,543.1 550.78,589.7 2891.72,609.1 3005.94,659.47 2613.22,727.92 1666.3,787.7 939.2,853.91 2249.44,860.4 2879.46,899.63 1367.86,905.76 148.3,1018.98 207.03,1020.32 262.58,1021.45 321.31,1022.8 380.03,1023.47 981.46,1073.58 1338.52,1075.89 148.3,1078.43 207.03,1079.78 262.58,1080.91 321.31,1082.25 380.03,1082.93 2992.23,1088.84 661.4,1125.21 262.92,1140.36 321.48,1141.71 380.03,1142.38 381.77,1197.45 262.92,1199.82 321.31,1199.45 2874.06,1225.12 3261.19,1231.92 3320.64,1231.59 3380.1,1231.59 749.4,1238.34 1213.18,1241.05 585.98,1243.37 3260.06,1287.48 3258.71,1346.2 2931.49,1366.32 1074.2,1418.33 1515.44,1465.86 1992.87,1490.93 2043.62,1490.93 2094.37,1490.93 2145.12,1490.93 2195.87,1490.93 2246.63,1490.93 1515.44,1517.75 1125.96,1542.09 1515.44,1569.63 1515.44,1621.52 794.65,1726.08 1214.51,1771.34 1095.32,1784.39 911.88,1800.26 495.92,1864 3040.81,1864
  other v2: 1276.6,1219.78 1323.85,1219.78 1300.22,1237.5 1276.6,1255.22 1323.85,1255.22 2821.39,1295.57 2786.94,1311.31 2855.84,1311.31 2821.39,1327.06
NetC1_1: C1.1 D3.1 L1.1 R4.2 U1.10 | length 327.9
  Top Layer w10: v1@1396.85,1445.63 1406.15,1445.63 1415.61,1436.17 C1.1
  Bottom Layer w10: v1(1381.67,1180.69) 1381.67,1436.32 v1@1392.93,1447.59
  other v1: 1394.4,1447.59
NetC1_2: C1.2 U1.1 | length 84.9
  Top Layer w10: U1.1 1339.59,1385.86 C1.2@1351.77,1398.05
NetC2_1: C2.1 C3.1 C4.1 J1.1 L1.2 R6.1 TP3.1 | length 1783.6
  Top Layer w20: R6.1@1155.01,803.09 1155.01,762.94 1178.35,739.6 TP3.1@1457.06,739.6
  Bottom Layer w20: TP3.1 2207.44,740.79 2397.57,930.92 J1.1
NetC5_1: C5.1 C9.1 D2.1 L2.1 R2.1 | length 720.1
  Top Layer w20: L2.1 940.75,1724.8 R2.1
  Top Layer w50: D2.1@356.59,1630.78 L2.1@944.16,1630.78
NetC6_1: C6.1 L2.2 R2.2 R3.1 | length 317.8
  Top Layer w20: R2.2 1037.53,1756.37 1066.73,1727.16 L2.2
  Top Layer w50: L2.2@1054.41,1619.97 R3.1@1241.64,1619.97
NetC7_1: C7.1 C8.1 R3.2 U1.2 | length 337.6
  Top Layer w10: U1.2 C8.1@1319.91,1479.44
  Top Layer w50: R3.2@1233.02,1550.12 1337.42,1550.12 ; C8.1@1340.37,1478.15 1340.37,1550.12
NetC10_1: C10.1 R4.1 | length 73.9
  Top Layer w50: R4.1@1582.82,1246.14 C10.1@1582.82,1320.08
NetC11_1: C11.1 U1.4 | length 183
  Top Layer w10: C11.1@1192.27,1421 1266.73,1421 1280.54,1407.19 U1.4
NetC12_1: C12.1 R9.2 U1.8 | length 193.3
  Top Layer w10: C12.1@1299.71,1030.65 1299.71,1031.72 U1.8@1299.71,1159.83
  Top Layer w20: R9.2@1239.12,1031.72 1299.71,1031.72 C12.1
NetC13_1: C13.1 R9.1 | length 60.2
  Top Layer w20: R9.1 C13.1@1298.8,965.19
NetC19_1: C19.1 U3.35 | length 97.3
  Top Layer w10: C19.1@2841.08,1165.79 U3.35@2841.08,1263.12
NetC20_1: C20.1 D6.2 D7.1 J6.1 R34.1 R35.2 | length 607.6
  Top Layer w20: J6.1 2352.68,377.6 2446.72,283.57 D7.1 D7.1@2472.36,283.57 ; C20.1 D7.1@2472.36,280.25 ; D7.1@2478.73,280.52 D6.2 ; R35.2@2603.62,194.72 D6.2@2603.62,271.39 ; D6.2@2614.31,278.97 R34.1
NetD1_1: D1.1 R1.1 | length 65.1
  Top Layer w20: R1.1@547.97,923.9 D1.1
NetD1_2: D1.2 U1.6 | length 844.8
  Top Layer w10: v1(1230.41,1113.92) 1252.48,1113.92 1260.85,1122.3 U1.6
  Top Layer w20: D1.2 748.88,1048.06 v3(829.35,967.6)
  Bottom Layer w20: v3(829.35,967.6) 989.44,967.6 1135.76,1113.92 v1(1230.41,1113.92)
NetD2_2: D2.2 J2.1 | length 264.2
  Top Layer w50: J2.1@187.35,1370.49 D2.2
NetD4_2: D4.2 R14.2 | length 96
  Top Layer w20: D4.2 R14.2@2117.59,379.36
NetD5_1: D5.1 R19.1 | length 66.2
  Top Layer w20: R19.1@2557.3,831.2 D5.1@2557.3,897.35
NetD5_2: D5.2 TP13.1 U3.31 | length 514.9
  Top Layer w10: v1(2744.8,1149.28) 2731.14,1162.95 2731.14,1264.64 2743.36,1276.87 U3.31
  Top Layer w20: D5.2 TP13.1@2556.72,1125
  Bottom Layer w10: TP13.1 2581,1149.28 v1(2744.8,1149.28)
NetJ3_1: J3.1 R12.1 | length 262
  Top Layer w50: J3.1@199.96,683.91 R12.1@461.97,683.91
NetJ4_2: J4.2 R13.2 TP4.1 U2.3 | length 907.2
  Top Layer w20: J4.2@886.2,381.93 886.2,603.36 ; 887.34,603.36 887.34,1080.3 1022.29,1215.25 1040.28,1215.25
NetJ4_4: J4.4 R15.1 TP5.1 U2.4 | length 766.7
  Top Layer w20: J4.4@987.5,380.63 TP5.1@987.5,606.93 ; TP5.1@997.11,608.05 988.29,616.87 988.29,983.41 1051.13,1046.25 1051.13,1118.74
NetR6_2: R6.2 R7.2 TP2.1 | length 374.9
  Top Layer w20: R7.2@1154.26,935.29 1154.26,866.09 1127.61,866.09 1104.42,842.9 1104.42,757.52 1209.02,652.93 TP2.1@1221.97,652.93
NetR7_1: R7.1 R10.2 R11.2 U1.7 | length 297.2
  Top Layer w10: R11.2@1176.76,1072.41 1249.74,1072.41 1279.76,1102.43 1279.76,1156.01 U1.7
  Top Layer w20: R10.2@1106.61,1001.82 1157.23,1001.82 1176.09,1020.68 R11.2@1176.09,1070.5
NetR8_2: R8.2 U1.5 | length 106.4
  Top Layer w10: R8.2@1187.29,1357.5 1249.87,1357.5 1260.22,1347.15 1260.22,1318.84 U1.5
NetR10_1: R10.1 U2.6 | length 76.8
  Top Layer w10: R10.1@1102.38,1065.41 U2.6@1102.38,1142.26
NetR17_1: R17.1 U3.5 U3.14 U3.15 U3.16 U3.17 U3.18 U3.26 U3.27 U3.38 | length 334.8
  Top Layer w10: 2653.13,1358.48 2753.56,1358.48 U3.27 ; R17.1 R17.1@2671.79,1378.08 ; R17.1@2674.57,1375.29 U3.26 U3.38@2797.24,1375.29 ; U3.38@2821.39,1422.57 2861.54,1382.42 2861.54,1366.98 2872.42,1356.1 U3.5@2884.85,1356.1
  other v2: 2821.39,1376.27 2786.94,1394.98 2855.84,1394.98 2821.39,1413.68 2786.94,1432.38 2855.84,1432.38 2821.39,1451.08 2786.94,1469.78 2855.84,1469.78 2821.39,1488.48
NetR18_1: R18.1 U4.3 | length 51.7
  Top Layer w7: R18.1@2824.38,491.12 U4.3
NetR20_1: R20.1 U3.3 | length 117
  Top Layer w10: U3.3 2933.24,1316.24 2960.78,1343.78 R20.1@2991.9,1343.78
NetR21_1: R21.1 U4.6 | length 65.4
  Top Layer w7: R21.1@2871.62,477.37 U4.6
NetR23_1: R23.1 U4.8 | length 81.5
  Top Layer w10: U4.8@2890.45,774.25 R23.1
NetR25_1: R25.1 U4.11 | length 81.6
  Top Layer w7: U4.11 2840.12,856.65
NetR27_2: R27.2 U3.2 | length 178.7
  Top Layer w10: U3.2 2932.63,1296.55 2950.84,1278.33 2989.13,1278.33
  Top Layer w20: R27.2@2990.27,1208.78 2990.27,1277.19
NetR28_2: R28.2 U3.34 | length 187.5
  Top Layer w10: R28.2@2806.39,1081.8 2806.39,1181.98 2821.39,1196.98 U3.34@2821.39,1263.12
OV: R16.1 R22.2 U3.1 U4.2 U4.5 U4.9 | length 968.1
  Top Layer w7: U4.2 2808.63,630.52 ; 2843.87,667.83 2855.87,655.83 U4.5 ; 2871.62,695.58 U4.9 2871.62,825.82
  Top Layer w10: 2807.59,631.55 2843.87,667.83 ; 2841.18,665.14 2871.62,695.58 ; 2871.62,825.82 2949.08,903.28 R22.2 R16.1@2949.08,1028.6 ; U3.1@2882.24,1276.79 2909.79,1276.79 2946.39,1240.18 R16.1@2946.39,1028.6
UVLO: R24.1 R26.2 U3.33 U4.12 | length 578.5
  Top Layer w7: 2782.21,864.17 2824.38,822.01 U4.12
  Top Layer w10: R24.1@2747.62,1021.25 2782.21,1021.25 ; 2782.21,864.17 2782.21,1021.25 ; U3.33@2801.71,1263.12 2801.71,1203.07 2782.21,1183.58 2782.21,1021.25 ; R26.2@2812.54,1021.25 2782.21,1021.25
V3.3: C14.1 C15.1 C16.1 D4.1 D6.1 J4.18 J4.20 R1.2 R12.2 R13.1 R15.2 R19.2 R29.2 R30.2 R31.2 R32.2 R33.2 U2.1 U4.14 | length 1210.4
  Top Layer w10: v1(995.55,1344.09) 1039.5,1344.09 1061.66,1321.94 C15.1 1095.14,1286.14 1101.91,1279.38 U2.1
  Top Layer w20: R1.2 547.3,796.01 v4(595.18,748.13) ; v1(791.09,1139.2) R13.1 ; R15.2@1050.79,931.33 v1(1107.41,931.33) ; J4.20 D4.1@1962.01,379.85 ; D4.1@1966.72,383.58 R33.2@1966.72,443.67 ; R19.2 2491.41,792.14 2498.55,785 ; D6.1 2612.76,373.52 2625.73,386.5 v1(2716.92,386.5) 2732.03,401.61 R31.2 ; v1(2619.57,850.39) 2631.5,838.46 R29.2 ; v1(2720.34,726.96) C16.1@2720.34,770.47 ; C16.1 2785.58,775.13
  Top Layer w50: R12.2@537.65,682.89 C14.1@618.35,682.89
  other v1: 2593.87,623.31 646.57,748.13 2520,785
V_ENC: C17.1 C18.1 J5.2 R34.2 U3.6 U3.7 U3.8 U3.9 U3.10 U3.11 U3.12 U3.13 U3.19 U3.20 U3.21 U3.22 U3.23 U3.24 | length 1723.8
  Top Layer w20: R34.2@2760,276.68 3071.88,276.68 3425.25,630.05 3425.25,1422.99 J5.2
VOUT_NP: J1.2 R16.2 R17.2 R20.2 R24.2 U3.29 | length 497.3
  Top Layer w10: R17.2@2660.83,1338.98 2662.2,1340.36 2711.18,1340.36 2735.3,1316.24 U3.29
  Top Layer w20: v1(2630.74,1084.67) R24.2@2683.9,1031.51 ; R17.2@2673.17,1315.71 R17.2@2673.17,1319.86 ; R16.2@3024.38,1030.07 3024.38,987.26 v1(3045.56,966.08) ; R20.2@3039.41,1343.93 v1(3098.72,1343.93)
  Top Layer w50: J1.2 2524.06,1320.48 R17.2
  other v1: 2716.93,1323.5
pads on no net: H1.0 H2.0 H3.0 H4.0 U3.25

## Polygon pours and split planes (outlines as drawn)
NetC7_1 on Top Layer "Top Layer-Vin" (solid, remove dead copper, pour order 18): 1293.84,1569.78 1333.72,1609.67 1345.35,1609.67 1345.35,1507.98 1338.48,1501.11 1324.74,1501.11 1294.11,1531.75
NetR17_1 on Top Layer "Top Layer-Drain1" (solid, remove dead copper, pour order 19): 2650.66,1354.31 2644.51,1360.34 2644.69,1401.21 2648.12,1404.65 2688.46,1404.65 2713.16,1379.95 2789.13,1379.95 2789.13,1369.95 2690.96,1369.95 2677.78,1356.84
V3.3 on Top Layer "Top Layer-V3-3-a" (solid, remove dead copper, pour order 24): 2650.01,690.81 2668.64,690.81 2670.75,688.7 2670.75,644.76 2690.08,625.42 2723.83,625.42 2727.34,621.91 2727.34,587.1 2723.13,582.88 2647.54,582.88 2625.75,604.68 2583.92,604.68 2573.37,615.23 2573.37,637.02 2626.8,690.46
GND on Top Layer "Top Layer-GND" (solid, remove dead copper, pour order 30): 52.14,1339.63 52.14,1566.11 400.65,1913.1 401.85,1913.1 398.26,1910.71 436.54,1950.18 3089.86,1950.5 3148.04,1892.32 3148.04,1744.8 3199.98,1692.86 3418.15,1692.86 3472.17,1638.83 3472.17,394.24 3432.69,354.76 3260.24,354.76 3148.04,242.56 3148.04,92.96 3100.25,45.17 3096.09,49.33 451.07,49.33 403.28,97.12 403.28,250.87 343.03,311.13 102,311.13 50.06,363.07 50.06,1339.63
V_ENC on Top Layer "Top Layer-No Net" (solid, remove dead copper, pour order 27): 2899.78,1468.1 3379.33,1468.1 3393.96,1482.74 3393.96,1569.76 3385.02,1578.7 2885.68,1578.7 2878.36,1571.39
NetC1_1 on Top Layer "Top Layer-SW8" (solid, pour order 26): 1740.22,1077.5 1740.22,1022.5 1740.22,1007.5 1715.22,982.5 1714.54,981.81 1482.23,981.81 1475.91,981.81 1465.22,992.5 1465.22,1032.5 1465.22,1042.5 1400.22,1107.5 1395.22,1112.5 1390.22,1117.5 1345.22,1117.5 1340.22,1122.5 1340.22,1187.5 1355.22,1202.5 1520.22,1202.5 1680.22,1202.5 1740.22,1142.5
NetC2_1 on Top Layer "Bottom Layer-Vout_8V" (solid, pour order 25): 2120.6,1381.92 1995.53,1381.92 1988.72,1374.75 1988.72,1026.86 2007.81,1006.48 2415.86,1006.61 2431.34,1023.15 2431.34,1371.44 2421.4,1381.81
V_ENC on Top Layer "Bottom Layer-voutfuse small" (solid, pour order 22): 2899.79,1579.8 2748.86,1579.8 2744.77,1576.52 2744.91,1404.65 2756.16,1400.88 2778.28,1401.4 2899.76,1367.94
NetR17_1 on Top Layer "Top Layer-Drain" (solid, pour order 21): 2776.39,1504.98 2866.39,1504.98 2866.39,1540.6 2861.95,1545.02 2779.09,1545.02 2776.39,1542.31
NetR25_1 on Top Layer "Top Layer-No Net 3" (solid, remove dead copper, pour order 20): 2809.4,873.23 2834.36,848.27 2844.7,848.27 2844.7,869.19 2830.26,883.63
V3.3 on Top Layer "Top Layer-V3_3" (solid, remove dead copper, pour order 23): 617.69,770.29 583.94,770.29 537.65,723.99 537.65,685.25 551.13,671.77 555.09,675.73 649.12,675.73 649.12,685.77 671.83,708.48 671.83,753.38 672.63,754.18 656.78,770.02 618.22,770.02
GND on Bottom Layer "Bottom Layer-GND" (solid, remove dead copper, pour order 29): 52.14,1339.63 52.14,1566.11 400.65,1913.1 401.85,1913.1 398.26,1910.71 436.54,1950.18 3089.86,1950.5 3148.04,1892.32 3148.04,1744.8 3199.98,1692.86 3418.15,1692.86 3472.17,1638.83 3472.17,394.24 3432.69,354.76 3260.24,354.76 3148.04,242.56 3148.04,92.96 3100.25,45.17 3096.09,49.33 451.07,49.33 403.28,97.12 403.28,250.87 343.03,311.13 102,311.13 50.06,363.07 50.06,1339.63
GND on mid layer 1-GND "mid layer 1-GND" (solid, remove dead copper, pour order 28): 51.37,1339.52 51.37,1566 399.89,1912.99 401.09,1912.99 397.5,1910.59 435.78,1950.07 3089.1,1950.39 3147.27,1892.21 3147.27,1744.69 3199.22,1692.74 3417.39,1692.74 3471.41,1638.72 3471.41,394.13 3431.93,354.65 3259.47,354.65 3147.27,242.45 3147.27,92.85 3099.48,45.06 3095.33,49.22 450.31,49.22 402.52,97 402.52,250.76 342.26,311.02 101.24,311.02 49.29,362.96 49.29,1339.52
VOUT_NP on mid layer 2-VCC "mid layer 2-VCC-vout-np" (solid, remove dead copper, pour order 16): 2748.83,1367.26 2665.18,1367.26 2611.88,1313.97 2611.88,1040.31 2710.05,942.15 3061.45,942.15 3122.08,1002.78 3122.08,1354.76 3119.25,1357.59 3109.44,1367.39 3006.57,1367.39
V3.3 on mid layer 2-VCC "mid layer 2-VCC-V3-3" (solid, remove dead copper, pour order 17): 567.97,955.23 567.97,995.66 947.1,1374.78 1016.92,1374.78 1139.86,1251.84 1141.57,1250.13 1141.57,729.42 1150.69,729.42 1187.83,692.28 2240.02,692.28 2425.7,877.97 2668.07,877.97 2869.39,676.65 2869.39,380.94 2869.39,376.52 2807.92,315.06 1621.62,315.06 991.07,315.06 566.94,739.19

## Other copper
Top Layer:
  pour cut-out: 1455.18,929.88 1678.63,929.88 1704.42,955.67 1682.78,977.32 1437.75,977.32 1426.93,966.49 1426.93,939.44 1436.98,929.39
  pour cut-out: 2998.39,1304.54 3009.56,1315.71 3036.47,1312.52 3035.49,1249.55 3036.45,1173.88 3034.47,1173.86 3007.97,1173.99 2998.39,1183.58
  pour cut-out: 1312.06,1112.01 1384.54,1112.01 1459.6,1036.95 1459.6,992.8 1482.78,969.62 1483.14,969.99 1493.45,969.99 1493.45,968.15 1455.18,929.88 1271.58,929.88 1264.22,937.24
  pour cut-out: 1093.36,1320.13 1094.19,1320.96 1163.69,1320.96 1163.69,1314.72 1163.27,1315.13 1092.53,1315.13
  pour cut-out: 1208.63,1136.61 1208.63,1163.66 1170.76,1201.53 1117.08,1201.53 1117.08,1219.84 1118.33,1221.09 1157.45,1221.09 1232.35,1146.18
  pour cut-out: 1645.84,1299.9 1654.86,1308.92 1977.26,1308.92 1980.83,1305.36 1980.83,1026.14 2012.05,994.92 2072.71,994.92 2072.71,892.34 2063.79,883.41 1680.21,883.41 1667.72,895.9 1667.72,974.4 1670.39,977.08 1720.35,977.08 1748.89,1005.63 1748.89,1143.89 1681.1,1211.69 1631.14,1211.69 1628.47,1209.01 1628.47,1278.59 1644.52,1294.65
  pour cut-out: 1620.69,1252.4 1620.69,1435.7 1634.17,1449.18 1654.84,1449.18 1660.28,1443.09 1660.23,1427.62 1660.23,1292.84 1623.39,1256
  pour cut-out: 1541.07,1222.62 1399.39,1222.62 1394.78,1227.23 1394.7,1329.39 1412.55,1347.17 1412.8,1283.4 1416.58,1279.62 1544.43,1279.62 1544.43,1223.45 1544.01,1223.04
  pour cut-out: 356.24,1887.7 356.24,1749.54 321.33,1714.63 191.34,1714.63 182.42,1723.54
  text ".Layer_Name" at -742.11,-1575.75 h60
mid layer 1-GND:
  pour cut-out: 356.24,1888.44 356.24,1750.28 321.33,1715.37 191.34,1715.37 182.42,1724.28
  text ".Layer_Name" at -741.72,-1575.77 h60
mid layer 2-VCC:
  pour cut-out: 356.24,1887.7 356.24,1749.54 321.33,1714.63 191.34,1714.63 182.42,1723.54
  text ".Layer_Name" at -742.11,-1575.75 h60
Bottom Layer:
  pour cut-out: 356.24,1887.7 356.24,1749.54 321.33,1714.63 191.34,1714.63 182.42,1723.54
  text ".Layer_Name" at -742.11,-1575.75 h60

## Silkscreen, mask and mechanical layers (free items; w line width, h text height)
Top Overlay:
  lines w10: 956.76,1181.27 956.76,1589.79 ; 959.83,893.39 959.83,706.67 1400.24,706.67 ; 961.48,972.69 961.48,1095.94 ; 1194.99,1663.07 3116.59,1663.07 3116.59,1057.78 ; 1521.72,705.93 1883.04,705.71 ; 1881.59,705.34 2019.84,705.34 ; 1893.65,253.83 1878.65,268.83 ; 1893.65,283.83 1878.65,268.83 ; 1921.98,268.83 1878.65,268.83 ; 2149.6,706.11 2263.91,706.11 ; 2386.71,707.66 2607.61,707.66 2607.61,509.86 ; 2607.38,376.85 2607.38,444.11 ; 2655.92,347.74 3116.59,347.74 ; 3115.97,346.2 3115.97,987.6
  text "Venc" at 3291.27,1632.11 h60
  text "24V" at 71.6,1499.62 h60
  text "GND" at 3299.64,1104.1 h56
  text "GND" at 126.98,937.71 h60
  text "3.3V" at 79.03,837.87 h60
  text "GND" at 129.04,306.6 h60
  text "TIDA-00180 REV E1" at 1345.53,36.44 h59.06
M1 Board Outline:
  the board outline again, w10
M5 Assembly Top:
  lines w10: -1611.11,-1647.42 4988.89,-1647.42 ; -1611.11,-1444.09 4990.89,-1444.09 ; -1611.11,-1240.76 -1611.11,-1850.76 2393.89,-1850.76 4990.89,-1850.76 4990.89,-1240.76 -1610.61,-1240.76 -1610.61,-1850.76 -35.11,-1850.76 ; 853.89,-1850.76 853.89,-1240.76 ; 2120.89,-1444.09 2120.89,-1240.76 ; 2960.89,-1444.09 2960.89,-1240.76 ; 3582.89,-1857.26 3582.89,-1654.42
  text "COMPONENTS MARKED 'DNP' SHOULD NOT BE POPULATED." at -165.61,-1035.76 h60
  text "ASSEMBLY VARIANT:" at -166.11,-1151.26 h60
  text ".VariantName" at 869.89,-1151.26 h60
  text "PCB VIEWED FROM TOP SIDE" at -1547.61,-1372.92 h60
  text "BOARD #:" at 928.89,-1372.92 h60
  text ".PRJ_Number" at 1474.39,-1372.92 h60
  text "REV:" at 2318.89,-1372.92 h60
  text ".PCB_Rev" at 2610.39,-1372.92 h60
  text "SVN REV:" at 3156.89,-1372.92 h60
  text ".VersionControl_RevNumber" at 3662.89,-1372.92 h60
  text "IGNORE ->" at -1547.61,-1575.75 h60
  text "PLOT NAME =" at -1547.61,-1781.59 h60
  text ".plot_File_Name" at -742.11,-1781.59 h60
  text "GENERATED    :" at 930.89,-1781.59 h60
  text ".Print_Date" at 1800.39,-1781.59 h60
  text ".Print_Time" at 2529.39,-1781.59 h60
  text "TEXAS INSTRUMENTS" at 3793.89,-1781.59 h60
M6 Assembly Bottom:
  lines w10: -1611.61,-1444.59 4990.39,-1444.59 ; -1609.61,-1647.92 4990.39,-1647.92 ; -203.61,-1857.76 -203.61,-1654.92 ; 418.39,-1444.59 418.39,-1241.26 ; 1258.39,-1444.59 1258.39,-1241.26 ; 2525.39,-1851.26 2525.39,-1241.26 ; 3414.39,-1851.26 4989.89,-1851.26 4989.89,-1241.26 -1611.61,-1241.26 -1611.61,-1851.26 985.39,-1851.26 4990.39,-1851.26 4990.39,-1241.26
  text "COMPONENTS MARKED 'DNP' SHOULD NOT BE POPULATED." at 4782.89,-1035.26 h60
  text ".VariantName" at 3738.89,-1151.26 h60
  text "ASSEMBLY VARIANT:" at 4777.89,-1151.26 h60
  text ".VersionControl_RevNumber" at -283.61,-1373.42 h60
  text "SVN REV:" at 222.39,-1373.42 h60
  text ".PCB_Rev" at 768.89,-1373.42 h60
  text "REV:" at 1060.39,-1373.42 h60
  text ".PRJ_Number" at 1904.89,-1373.42 h60
  text "BOARD #:" at 2450.39,-1373.42 h60
  text "PCB VIEWED FROM BOTTOM SIDE" at 4926.89,-1373.42 h60
  text "IGNORE ->" at 1228.75,-1575.75 h60
  text "TEXAS INSTRUMENTS" at -414.61,-1782.09 h60
  text ".Print_Time" at 849.89,-1782.09 h60
  text ".Print_Date" at 1578.89,-1782.09 h60
  text "GENERATED    :" at 2448.39,-1782.09 h60
  text ".plot_File_Name" at 4121.39,-1782.09 h60
  text "PLOT NAME =" at 4926.89,-1782.09 h60
M9 Title Sheet:
  drawing of 57 lines, arcs and shapes, not listed
  text "1" at -579.27,7319.24 h70
  text "2" at 1916.39,7319.24 h70
  text "3" at 4405.74,7319.24 h70
  text "4" at 6912.4,7319.24 h70
  text "5" at 9411.39,7319.24 h70
  text "6" at 11916.39,7319.24 h70
  text "A" at 13132.39,6832.54 h70
  text "A" at -1735.61,6176.24 h70
  text "B" at -1735.61,3796.24 h70
  text "B" at 13064.39,3796.24 h70
  text "C" at -1735.61,1421.24 h70
  text "PROJECT TITLE:" at 10024.39,-439.76 h45
  text ".PRJ_Title" at 10074.39,-573.08 h70
  text "DESIGNED FOR:" at 10024.39,-740.76 h45
  text ".PRJ_Customer" at 10074.39,-880.76 h70
  text "D" at 13064.39,-948.76 h70
  text "FILE NAME:" at 10024.39,-1040.76 h45
  text ".PCB_File_Name_No_Path" at 10074.39,-1160.76 h70
  text "Texas Instruments (TI) and/or its licensors do not warrant the accuracy or completeness of this specification" at 5054.89,-1322.6 h45
  text "ENGINEER:" at 10024.39,-1330.76 h45
  text "LAYOUT BY:" at 11529.39,-1330.76 h45
  text "or any information contained therein. TI and/or its licensors do not warrant that this design will meet" at 5009.91,-1435.26 h45
  text ".PRJ_Engineer" at 10074.39,-1485.75 h70
  text ".PCB_Layout" at 11579.89,-1485.75 h70
  text "the specifications, will be suitable for your application or fit for any particular purpose, or will operate in" at 5009.91,-1547.93 h45
  text "ALTIUM DESIGNER VERSION:" at 11529.39,-1640.76 h45
  text "an implementation. TI and/or its licensors do not warrant that the design is production worthy. You should" at 5009.91,-1660.59 h45
  text "completely validate and test your design implementation to confirm the system functionality for your application." at 5054.89,-1773.26 h45
  text ".print_Scale" at 10074.39,-1774.08 h70
  text ".Application_BuildNumber" at 11579.89,-1774.08 h70
  text "2" at 1916.39,-1980.76 h70
  text "3" at 4405.74,-1980.76 h70
  text "4" at 6912.4,-1980.76 h70
  text "5" at 9411.39,-1980.76 h70
  text "6" at 11916.39,-1980.76 h70
M11 Gerber Information:
  lines w10: -1611.11,-1647.42 4988.89,-1647.42 ; -1611.11,-1444.09 4990.89,-1444.09 ; -1611.11,-1240.76 -1611.11,-1850.76 2393.89,-1850.76 4990.89,-1850.76 4990.89,-1240.76 -1610.61,-1240.76 -1610.61,-1850.76 -35.11,-1850.76 ; 853.89,-1850.76 853.89,-1240.76 ; 2120.89,-1444.09 2120.89,-1240.76 ; 2960.89,-1444.09 2960.89,-1240.76 ; 3582.89,-1857.26 3582.89,-1654.42
  text "ALL ARTWORK VIEWED FROM TOP SIDE" at -1547.61,-1372.92 h60
  text "BOARD #:" at 928.89,-1372.92 h60
  text ".PRJ_Number" at 1474.39,-1372.92 h60
  text "REV:" at 2318.89,-1372.92 h60
  text ".PCB_Rev" at 2610.39,-1372.92 h60
  text "SVN REV:" at 3156.89,-1372.92 h60
  text ".VersionControl_RevNumber" at 3662.89,-1372.92 h60
  text "LAYER NAME =" at -1547.61,-1575.75 h60
  text "PLOT NAME =" at -1547.61,-1781.59 h60
  text ".plot_File_Name" at -742.11,-1781.59 h60
  text "GENERATED    :" at 930.89,-1781.59 h60
  text ".Print_Date" at 1800.39,-1781.59 h60
  text ".Print_Time" at 2529.39,-1781.59 h60
  text "TEXAS INSTRUMENTS" at 3793.89,-1781.59 h60

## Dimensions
3535,2012 to 3535,0 on M2 Board Dimensions
3535,2012 to 0,2012 on M2 Board Dimensions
